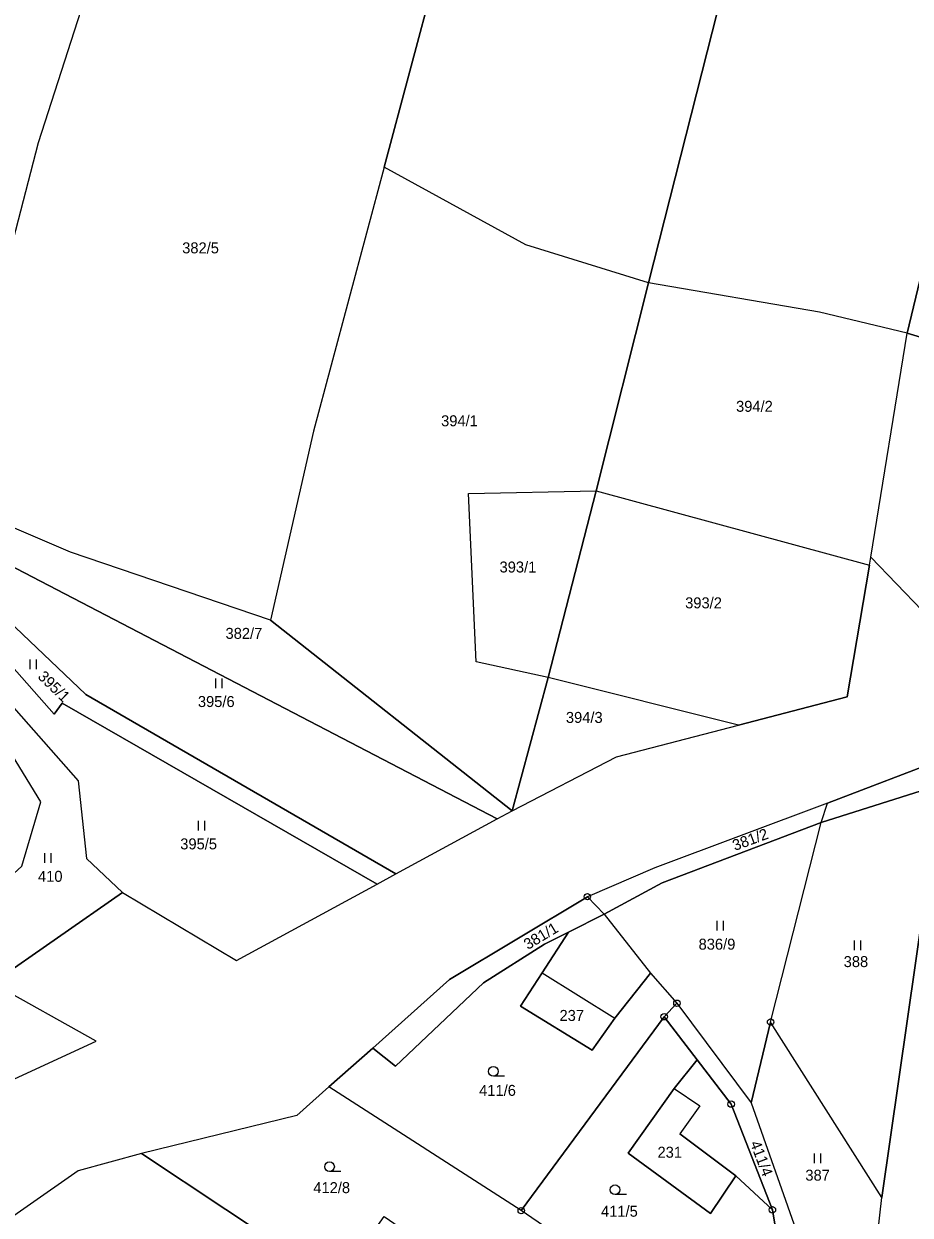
# Model space of a CAD drawing. Extents: x -654083 to -650132, y -1099819 to -1096699.
# Drawn here: x -652195.2 to -652058, y -1098317.8 to -1098133.4 of the extents above; entities that cross this region are included whole.
import ezdxf

# ---------------------------------------------------------------- set-up
doc = ezdxf.new("R2010")
doc.units = 0
for name, color, linetype in [('Geodetické body', 7, 'Continuous'), ('Hranice - vnitř_ kresba', 7, 'Continuous'), ('Obvody jako plochy', 7, 'Continuous'), ('Parcelní čísla', 7, 'Continuous'), ('Značky kultur', 7, 'Continuous')]:
    doc.layers.add(name, color=color, linetype=linetype)

msp = doc.modelspace()

# ---------------------------------------------------------------- linework, layer by layer
at = {"layer": 'Geodetické body'}
for centre, radius in [((-652107.95, -1098268.51), 0.5), ((-652107.95, -1098268.51), 0.001), ((-652094.08, -1098285), 0.5), ((-652094.08, -1098285), 0.001), ((-652096.05, -1098287.09), 0.5), ((-652096.05, -1098287.09), 0.001), ((-652079.58, -1098287.91), 0.5), ((-652079.58, -1098287.91), 0.001), ((-652085.69, -1098300.61), 0.5), ((-652085.69, -1098300.61), 0.001), ((-652118.18, -1098317.1), 0.5), ((-652079.31, -1098316.98), 0.5), ((-652118.18, -1098317.1), 0.001), ((-652079.31, -1098316.98), 0.001)]:
    msp.add_circle(centre, radius, dxfattribs=at)
at = {"layer": 'Hranice - vnitř_ kresba'}
for p, q in [((-652114.95, -1098280.31), (-652103.67, -1098287.32)), ((-652094.51, -1098298.22), (-652090.52, -1098300.88)), ((-652090.52, -1098300.88), (-652093.63, -1098305.22)), ((-652084.95, -1098311.72), (-652093.63, -1098305.22))]:
    msp.add_line(p, q, dxfattribs=at)
at = {"layer": 'Obvody jako plochy'}
for points in [[(-652021.07, -1098017.35), (-652020.94, -1098025.36), (-652058.45, -1098181.32), (-652072.02, -1098178.04), (-652098.48, -1098173.49), (-652059.78, -1098021.1), (-652040.03, -1098018.88)], [(-652059.78, -1098021.1), (-652098.48, -1098173.49), (-652117.45, -1098167.63), (-652139.42, -1098155.62), (-652131.47, -1098125.85), (-652123.39, -1098093.14), (-652111.64, -1098049.2), (-652106.55, -1098024.5), (-652090.27, -1098024.04)], [(-652016.68, -1098069.68), (-652043.35, -1098185.84), (-652058.45, -1098181.32), (-652020.94, -1098025.36), (-652003.46, -1098021.95)], [(-652201.88, -1098186.29), (-652192.91, -1098151.79), (-652181.27, -1098115.57), (-652200.13, -1098108.86), (-652212.68, -1098138.68), (-652232.98, -1098198.84), (-652229.19, -1098200.51), (-652222.75, -1098200.4), (-652219.9, -1098203.08), (-652210.52, -1098205.53)], [(-652139.42, -1098155.62), (-652150.32, -1098196.47), (-652157.01, -1098225.71), (-652187.94, -1098215.21), (-652210.52, -1098205.53), (-652201.88, -1098186.29), (-652192.91, -1098151.79), (-652181.27, -1098115.57), (-652172.13, -1098115.21), (-652166.56, -1098115.62), (-652165.08, -1098113.69), (-652131.47, -1098125.85)], [(-652117.45, -1098167.63), (-652139.42, -1098155.62), (-652150.32, -1098196.47), (-652157.01, -1098225.71), (-652119.58, -1098255.21), (-652114.02, -1098234.57), (-652125.14, -1098232.18), (-652126.33, -1098206.11), (-652106.61, -1098205.72), (-652098.48, -1098173.49)], [(-652072.02, -1098178.04), (-652098.48, -1098173.49), (-652106.61, -1098205.72), (-652064.28, -1098217.22), (-652064.08, -1098215.97), (-652058.45, -1098181.32)], [(-652043.35, -1098185.84), (-652049.67, -1098227.08), (-652052.14, -1098228.35), (-652064.08, -1098215.97), (-652058.45, -1098181.32)], [(-652221.41, -1098212.35), (-652212.54, -1098215.33), (-652190.5, -1098240.25), (-652189.26, -1098238.54), (-652140.51, -1098266.57), (-652137.6, -1098264.99), (-652185.59, -1098237.21), (-652205.26, -1098218.57), (-652215.35, -1098207.89), (-652229.19, -1098200.51), (-652233.69, -1098200.51), (-652236.2, -1098211.27), (-652246.13, -1098215.31), (-652253.12, -1098224.54), (-652260.73, -1098231.76), (-652244.73, -1098249.35), (-652229.13, -1098255.97), (-652216.25, -1098250.45), (-652208.75, -1098239.51), (-652214.85, -1098224.82), (-652218.27, -1098220.54), (-652226.95, -1098210.58)], [(-652119.58, -1098255.21), (-652157.01, -1098225.71), (-652187.94, -1098215.21), (-652210.52, -1098205.53), (-652219.9, -1098203.08), (-652215.35, -1098207.89), (-652121.92, -1098256.48)], [(-652106.61, -1098205.72), (-652114.02, -1098234.57), (-652125.14, -1098232.18), (-652126.33, -1098206.11)], [(-652067.72, -1098237.6), (-652084.53, -1098241.97), (-652114.02, -1098234.57), (-652106.61, -1098205.72), (-652064.28, -1098217.22)], [(-652121.92, -1098256.48), (-652215.35, -1098207.89), (-652205.26, -1098218.57), (-652185.59, -1098237.21), (-652137.6, -1098264.99)], [(-652214.85, -1098224.82), (-652208.75, -1098239.51), (-652216.25, -1098250.45), (-652229.13, -1098255.97), (-652244.73, -1098249.35), (-652260.73, -1098231.76), (-652235.99, -1098266.05), (-652235.79, -1098267.42), (-652212.12, -1098274.46), (-652214.09, -1098276.33), (-652211.07, -1098278.02), (-652195.49, -1098263.78), (-652192.54, -1098253.81), (-652212.15, -1098221.87), (-652217.6, -1098215.71), (-652221.41, -1098212.35), (-652226.95, -1098210.58), (-652218.27, -1098220.54)], [(-652179.91, -1098267.88), (-652162.28, -1098278.39), (-652140.51, -1098266.57), (-652189.26, -1098238.54), (-652190.5, -1098240.25), (-652212.54, -1098215.33), (-652221.41, -1098212.35), (-652217.6, -1098215.71), (-652212.15, -1098221.87), (-652186.77, -1098250.57), (-652185.48, -1098262.61)], [(-652185.48, -1098262.61), (-652179.91, -1098267.88), (-652200.06, -1098281.92), (-652211.07, -1098278.02), (-652195.49, -1098263.78), (-652192.54, -1098253.81), (-652212.15, -1098221.87), (-652186.77, -1098250.57)], [(-651884.84, -1098229.32), (-651841.12, -1098228.91), (-651840.96, -1098232.87), (-651853.75, -1098232.88), (-651884.99, -1098232.48), (-651916.16, -1098234.22), (-652012.33, -1098238.3), (-652038.62, -1098246.71), (-652053.2, -1098251.17), (-652071.74, -1098257.04), (-652070.75, -1098254.03), (-652052.15, -1098246.92), (-652013.72, -1098235.51), (-651916.23, -1098230.84)], [(-652084.53, -1098241.97), (-652114.02, -1098234.57), (-652119.58, -1098255.21), (-652103.46, -1098246.87)], [(-651990.64, -1098257.85), (-651961.81, -1098260.11), (-651942.87, -1098264.41), (-651920.72, -1098264.37), (-651921.21, -1098268.6), (-651924.5, -1098296.12), (-651926.51, -1098324.4), (-651926.72, -1098337.66), (-651926.66, -1098347.52), (-652044.74, -1098355.09), (-652063.02, -1098321.01), (-652062.36, -1098315.09), (-652053.2, -1098251.17), (-652038.62, -1098246.71), (-652023.38, -1098255.1)], [(-652071.74, -1098257.04), (-652053.2, -1098251.17), (-652062.36, -1098315.09), (-652079.58, -1098287.91)], [(-652070.75, -1098254.03), (-652097.49, -1098264.03), (-652107.95, -1098268.51), (-652105.33, -1098271.21), (-652096.35, -1098266.35), (-652071.74, -1098257.04)], [(-652082.6, -1098300.44), (-652079.58, -1098287.91), (-652071.74, -1098257.04), (-652096.35, -1098266.35), (-652105.33, -1098271.21), (-652098.16, -1098280.34), (-652094.08, -1098285)], [(-652107.95, -1098268.51), (-652105.33, -1098271.21), (-652110.88, -1098274), (-652114.59, -1098275.86), (-652124.02, -1098281.85), (-652137.64, -1098294.74), (-652141.15, -1098291.96), (-652129.28, -1098281.32)], [(-652105.33, -1098271.21), (-652098.16, -1098280.34), (-652103.67, -1098287.32), (-652107.18, -1098292.27), (-652118.3, -1098285.47), (-652114.95, -1098280.31), (-652110.88, -1098274)], [(-652141.15, -1098291.96), (-652137.64, -1098294.74), (-652124.02, -1098281.85), (-652114.59, -1098275.86), (-652110.88, -1098274), (-652114.95, -1098280.31), (-652118.3, -1098285.47), (-652107.18, -1098292.27), (-652103.67, -1098287.32), (-652098.16, -1098280.34), (-652094.08, -1098285), (-652096.05, -1098287.09), (-652118.18, -1098317.1), (-652147.98, -1098297.94)], [(-652220.74, -1098307.8), (-652183.99, -1098290.88), (-652200.06, -1098281.92), (-652211.07, -1098278.02), (-652214.09, -1098276.33), (-652239.79, -1098300.76), (-652241.65, -1098302.5)], [(-652114.95, -1098280.31), (-652103.67, -1098287.32), (-652107.18, -1098292.27), (-652118.3, -1098285.47)], [(-652075.08, -1098321.77), (-652075.39, -1098325.99), (-652076.86, -1098330.98), (-652079.5, -1098330.92), (-652078.19, -1098323.5), (-652079.31, -1098316.98), (-652085.69, -1098300.61), (-652090.93, -1098293.77), (-652096.05, -1098287.09), (-652094.08, -1098285), (-652082.6, -1098300.44)], [(-652096.05, -1098287.09), (-652090.93, -1098293.77), (-652094.51, -1098298.22), (-652101.62, -1098308.18), (-652088.88, -1098317.52), (-652084.95, -1098311.72), (-652079.31, -1098316.98), (-652078.19, -1098323.5), (-652079.5, -1098330.92), (-652079.11, -1098342.4), (-652109.61, -1098322.94), (-652118.18, -1098317.1)], [(-652076.86, -1098330.98), (-652063.02, -1098321.01), (-652062.36, -1098315.09), (-652079.58, -1098287.91), (-652082.6, -1098300.44), (-652075.08, -1098321.77), (-652075.39, -1098325.99)], [(-652085.69, -1098300.61), (-652079.31, -1098316.98), (-652084.95, -1098311.72), (-652088.88, -1098317.52), (-652101.62, -1098308.18), (-652094.51, -1098298.22), (-652090.93, -1098293.77)], [(-652127.77, -1098335.54), (-652121.05, -1098339.82), (-652109.61, -1098322.94), (-652118.18, -1098317.1), (-652147.98, -1098297.94), (-652152.94, -1098302.4), (-652176.99, -1098308.27), (-652150.85, -1098325.58), (-652146.77, -1098328.41), (-652139.42, -1098318), (-652134.77, -1098321.21), (-652123.19, -1098329.21), (-652126.64, -1098334.02)], [(-652088.88, -1098317.52), (-652101.62, -1098308.18), (-652094.51, -1098298.22), (-652090.52, -1098300.88), (-652093.63, -1098305.22), (-652084.95, -1098311.72)], [(-652181.03, -1098342.49), (-652170.94, -1098327.01), (-652158.52, -1098336.49), (-652150.85, -1098325.58), (-652176.99, -1098308.27), (-652186.79, -1098310.96), (-652202.08, -1098321.61), (-652206.66, -1098327.84), (-652189.68, -1098336.44)]]:
    msp.add_lwpolyline(points, close=True, dxfattribs=at)
for points in [[(-652246.48, -1098301.27), (-652241.65, -1098302.5), (-652220.74, -1098307.8), (-652183.99, -1098290.88), (-652200.06, -1098281.92), (-652179.91, -1098267.88), (-652162.28, -1098278.39), (-652140.51, -1098266.57), (-652137.6, -1098264.99), (-652121.92, -1098256.48), (-652119.58, -1098255.21), (-652103.46, -1098246.87), (-652084.53, -1098241.97), (-652067.72, -1098237.6), (-652064.28, -1098217.22), (-652064.08, -1098215.97), (-652052.14, -1098228.35)], [(-652052.15, -1098246.92), (-652070.75, -1098254.03), (-652097.49, -1098264.03), (-652107.95, -1098268.51), (-652129.28, -1098281.32), (-652141.15, -1098291.96), (-652147.98, -1098297.94), (-652152.94, -1098302.4), (-652176.99, -1098308.27), (-652186.79, -1098310.96), (-652202.08, -1098321.61)]]:
    msp.add_lwpolyline(points, dxfattribs=at)
at = {"layer": 'Značky kultur'}
for p, q in [((-652194.24, -1098231.81), (-652194.24, -1098233.31)), ((-652193.21, -1098233.31), (-652193.21, -1098231.81)), ((-652165.51, -1098234.73), (-652165.51, -1098236.23)), ((-652164.48, -1098236.23), (-652164.48, -1098234.73)), ((-652168.2, -1098256.76), (-652168.2, -1098258.26)), ((-652167.18, -1098258.26), (-652167.18, -1098256.76)), ((-652191.97, -1098261.77), (-652191.97, -1098263.27)), ((-652190.95, -1098263.27), (-652190.95, -1098261.77)), ((-652087.89, -1098272.25), (-652087.89, -1098273.75)), ((-652086.86, -1098273.75), (-652086.86, -1098272.25)), ((-652066.66, -1098275.27), (-652066.66, -1098276.77)), ((-652065.64, -1098276.77), (-652065.64, -1098275.27)), ((-652120.75, -1098296.3), (-652122.5, -1098296.3)), ((-652072.82, -1098308.24), (-652072.82, -1098309.74)), ((-652071.8, -1098309.74), (-652071.8, -1098308.24)), ((-652146.11, -1098311.05), (-652147.86, -1098311.05)), ((-652101.91, -1098314.62), (-652103.66, -1098314.62))]:
    msp.add_line(p, q, dxfattribs=at)
for centre in [(-652122.5, -1098295.55), (-652147.86, -1098310.3), (-652103.66, -1098313.87)]:
    msp.add_circle(centre, 0.75, dxfattribs=at)

# ---------------------------------------------------------------- texts
at = {"layer": 'Parcelní čísla'}
for s, p in [('382/5', (-652170.67, -1098168.95)), ('394/2', (-652084.93, -1098193.47)), ('394/1', (-652130.59, -1098195.71)), ('393/1', (-652121.54, -1098218.34)), ('393/2', (-652092.81, -1098223.89)), ('382/7', (-652163.96, -1098228.61)), ('395/6', (-652168.24, -1098239.16)), ('394/3', (-652111.27, -1098241.62)), ('395/5', (-652170.97, -1098261.19)), ('410', (-652192.99, -1098266.21)), ('836/9', (-652090.73, -1098276.71)), ('388', (-652068.27, -1098279.41)), ('237', (-652112.26, -1098287.74)), ('411/6', (-652124.7, -1098299.34)), ('231', (-652097.09, -1098308.91)), ('387', (-652074.2, -1098312.46)), ('412/8', (-652150.37, -1098314.39)), ('411/5', (-652105.83, -1098318.04))]:
    msp.add_text(s, height=1.7, dxfattribs=at).set_placement(p)
for s, rotation, p in [('395/1', 315.9, (-652193.15, -1098234.59)), ('381/2', 20.259, (-652085.11, -1098261.44)), ('381/1', 30.996, (-652117.16, -1098276.78)), ('411/4', 290.916, (-652082.8, -1098306.66))]:
    msp.add_text(s, height=1.7, rotation=rotation, dxfattribs=at).set_placement(p)

doc.saveas('drawing.dxf')
